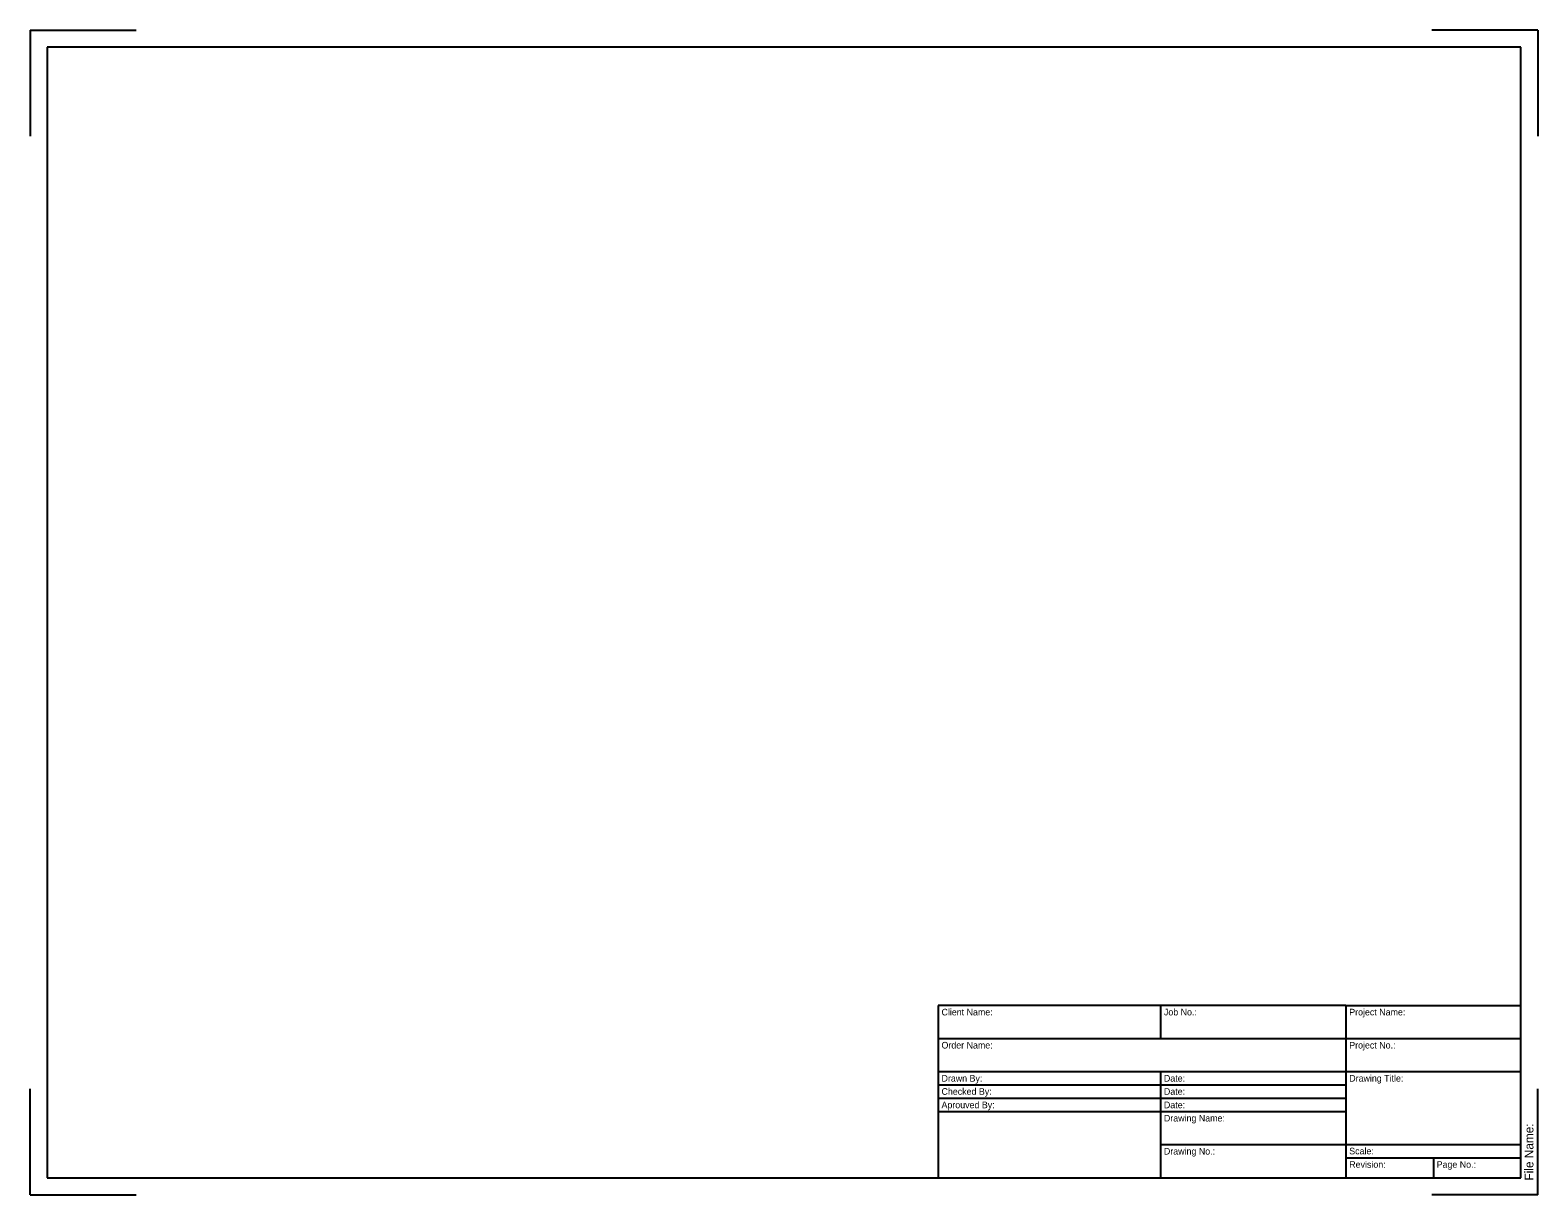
# Model space of a CAD drawing. Extents: x 0 to 3.67, y 0 to 2.83.
import ezdxf

# ---------------------------------------------------------------- set-up
doc = ezdxf.new("R2010")
doc.units = 0
doc.layers.add('STSF-BORDER', color=7, linetype='Continuous')

msp = doc.modelspace()

# ---------------------------------------------------------------- linework, layer by layer
at = {"layer": 'STSF-BORDER'}
for p, q in [((0, 2.8333), (0, 2.5758)), ((0, 2.8333), (0.2576, 2.8333)), ((3.6667, 2.8333), (3.4091, 2.8333)), ((3.6667, 2.8333), (3.6667, 2.5758)), ((0.0417, 2.7917), (0.0417, 0.0417)), ((3.625, 2.7917), (0.0417, 2.7917)), ((3.625, 0.0417), (3.625, 2.7917)), ((2.2083, 0.4607), (2.2083, 0.0417)), ((3.2, 0.4607), (2.2083, 0.4607)), ((2.7492, 0.4607), (2.7492, 0.3802)), ((3.2, 0.4607), (3.625, 0.4607)), ((3.2, 0.4607), (3.2, 0.0417)), ((2.2083, 0.3802), (3.2, 0.3802)), ((3.2, 0.3802), (3.625, 0.3802)), ((2.2083, 0.2997), (3.2, 0.2997)), ((2.7492, 0.2997), (2.7492, 0.0417)), ((3.2, 0.2997), (3.625, 0.2997)), ((0, 0), (0, 0.2576)), ((2.2083, 0.2675), (2.7492, 0.2675)), ((2.7492, 0.2675), (3.2, 0.2675)), ((3.6667, 0), (3.6667, 0.2576)), ((2.2083, 0.2353), (2.7492, 0.2353)), ((2.7492, 0.2353), (3.2, 0.2353)), ((2.2083, 0.2027), (2.7492, 0.2027)), ((2.7492, 0.2027), (3.2, 0.2027)), ((2.7492, 0.1222), (3.2, 0.1222)), ((3.2, 0.1226), (3.625, 0.1226)), ((3.2, 0.0904), (3.625, 0.0904)), ((3.4125, 0.0904), (3.4125, 0.0417)), ((0.0417, 0.0417), (3.625, 0.0417)), ((2.7492, 0.0417), (3.2, 0.0417)), ((0, 0), (0.2576, 0)), ((3.6667, 0), (3.4091, 0))]:
    msp.add_line(p, q, dxfattribs=at)

# ---------------------------------------------------------------- texts
for s, height, p in [('Client Name:', 0.016098, (2.2164, 0.4365)), ('Job No.:', 0.0161, (2.7573, 0.4365)), ('Project Name:', 0.016098, (3.208, 0.4365)), ('Order Name:', 0.016098, (2.2164, 0.356)), ('Project No.:', 0.016098, (3.208, 0.356)), ('Checked By:', 0.016098, (2.2164, 0.2434)), ('Drawn By:', 0.0161, (2.2164, 0.2755)), ('Date:', 0.0161, (2.7573, 0.2755)), ('Date:', 0.0161, (2.7573, 0.2434)), ('Drawing Title:', 0.016098, (3.208, 0.2755)), ('Aprouved By:', 0.016098, (2.2164, 0.2107)), ('Date:', 0.0161, (2.7573, 0.2107)), ('Drawing Name:', 0.016098, (2.7573, 0.1785)), ('Drawing No.:', 0.016098, (2.7573, 0.098)), ('Scale:', 0.0161, (3.208, 0.0985)), ('Revision:', 0.0161, (3.208, 0.0658)), ('Page No.:', 0.0161, (3.4205, 0.0658))]:
    msp.add_text(s, height=height, dxfattribs=at).set_placement(p)
msp.add_text('File Name:', height=0.02146, rotation=90, dxfattribs=at).set_placement((3.6559, 0.0349))

doc.saveas('drawing.dxf')
